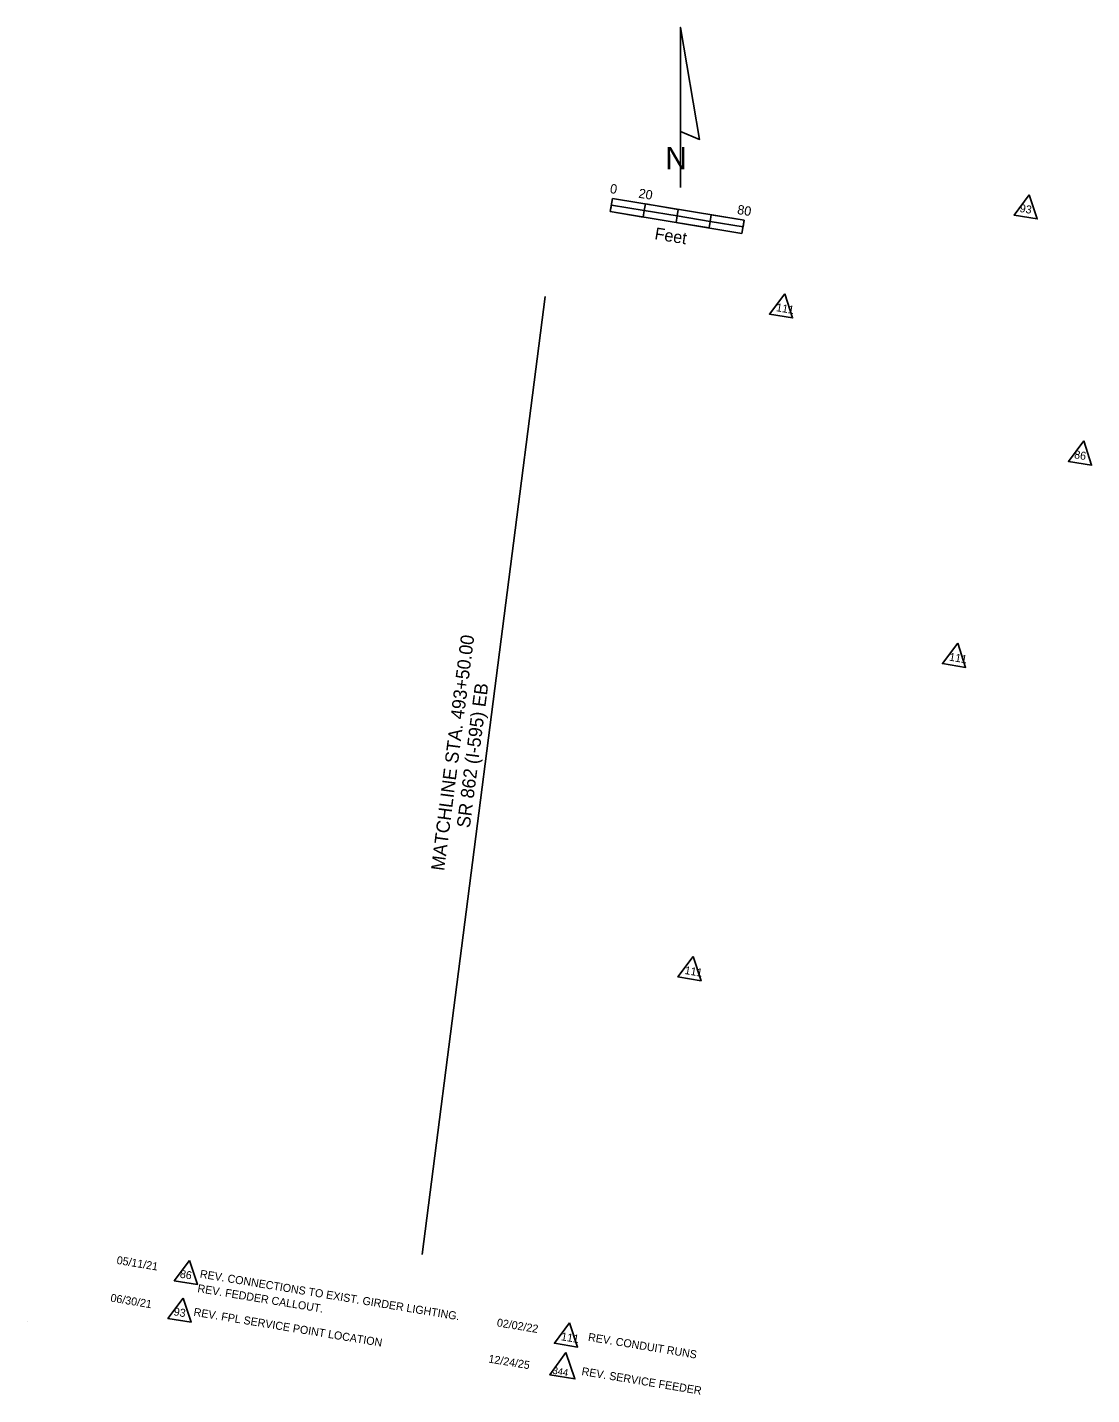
# Model space of a CAD drawing. Extents: x 927483 to 928746, y 636242 to 637203.
# Drawn here: x 927483 to 928122, y 636383 to 637203 of the extents above; entities that cross this region are included whole.
import ezdxf

# ---------------------------------------------------------------- set-up
doc = ezdxf.new("R2010")
doc.units = 0
for name, color, linetype in [('Cloud_dp', 7, 'Continuous'), ('NorthArw_dp', 7, 'Continuous'), ('PlotBorder_dp', 7, 'Continuous'), ('Scale_dp', 7, 'Continuous'), ('TextMinor', 7, 'Continuous')]:
    doc.layers.add(name, color=color, linetype=linetype)

msp = doc.modelspace()

# ---------------------------------------------------------------- linework, layer by layer
at = {"layer": 'Cloud_dp'}
for points in [[(928084.3, 637102.26), (928075.15, 637090.02), (928089.05, 637087.73)], [(927937.65, 637042.9), (927928.5, 637030.67), (927942.39, 637028.37)], [(928116.97, 636954.6), (928107.81, 636942.36), (928121.71, 636940.07)], [(928041.37, 636833.37), (928032.22, 636821.14), (928046.12, 636818.85)], [(927882.74, 636645.45), (927873.59, 636633.22), (927887.49, 636630.92)], [(927580.68, 636463.27), (927571.53, 636451.03), (927585.42, 636448.74)], [(927576.96, 636440.67), (927567.8, 636428.43), (927581.7, 636426.14)], [(927808.67, 636425.85), (927799.52, 636413.61), (927813.41, 636411.32)], [(927806.37, 636408.06), (927796.74, 636394.71), (927811.86, 636392.21)]]:
    msp.add_lwpolyline(points, close=True, dxfattribs=at)
at = {"layer": 'NorthArw_dp'}
msp.add_line((927875.11, 637106.63), (927875.11, 637202.63), dxfattribs=at)
msp.add_lwpolyline([(927875.11, 637140.23), (927875.11, 637202.63), (927886.63, 637135.43)], close=True, dxfattribs=at)
at = {"layer": 'PlotBorder_dp'}
msp.add_line((927794.09, 637041.24), (927720.24, 636466.75), dxfattribs=at)
at = {"layer": 'Scale_dp'}
for p, q in [((927834.37, 637100.01), (927833.07, 637092.11)), ((927913.31, 637086.99), (927834.37, 637100.01)), ((927833.07, 637092.11), (927912, 637079.1)), ((927912, 637079.1), (927913.31, 637086.99))]:
    msp.add_line(p, q, dxfattribs=at)
for points in [[(927853.45, 637092.81), (927854.11, 637096.75), (927873.84, 637093.5), (927873.19, 637089.55)], [(927833.07, 637092.11), (927833.72, 637096.06), (927853.45, 637092.81), (927852.8, 637088.86)], [(927872.54, 637085.61), (927873.19, 637089.55), (927892.92, 637086.3), (927892.27, 637082.35)], [(927892.92, 637086.3), (927893.57, 637090.25), (927913.31, 637086.99), (927912.66, 637083.05)]]:
    msp.add_lwpolyline(points, close=True, dxfattribs=at)
at = {"layer": 'TextMinor'}
msp.add_line((927483.47, 636426.68), (927483.47, 636426.68), dxfattribs=at)

# ---------------------------------------------------------------- texts
at = {"layer": 'Cloud_dp'}
for s, height, p in [('93', 4.8, (928078.28, 637091.95)), ('111', 4.8, (927932.25, 637032.49)), ('86', 4.8, (928110.95, 636944.29)), ('111', 4.8, (928035.98, 636822.96)), ('111', 4.8, (927877.35, 636635.04)), ('05/11/21', 4.8, (927536.77, 636461.2)), ('86', 4.8, (927574.66, 636452.96)), ('REV. CONNECTIONS TO EXIST. GIRDER LIGHTING. ', 4.8, (927586.68, 636452.97)), ('REV. FEDDER CALLOUT.', 4.8, (927585.24, 636444.29)), ('06/30/21', 4.8, (927533.05, 636438.6)), ('93', 4.8, (927570.93, 636430.36)), ('REV. FPL SERVICE POINT LOCATION', 4.8, (927582.91, 636430.14)), ('02/02/22', 4.8, (927764.76, 636423.78)), ('111', 4.8, (927803.27, 636415.44)), ('REV. CONDUIT RUNS', 4.8, (927819.47, 636415.08)), ('12/24/25', 4.8, (927759.73, 636402.07)), ('344', 4.2, (927798.19, 636395.32)), ('REV. SERVICE FEEDER', 4.8, (927815.58, 636394.55))]:
    msp.add_text(s, height=height, rotation=350.63813, dxfattribs=at).set_placement(p)
at = {"layer": 'NorthArw_dp'}
msp.add_text('N', height=13.43, dxfattribs=at).set_placement((927865.99, 637117.5))
at = {"layer": 'PlotBorder_dp'}
for s, p in [('MATCHLINE STA. 493+50.00', (927733.41, 636696.57)), ('SR 862 (I-595) EB', (927748.81, 636722.24))]:
    msp.add_text(s, height=8, rotation=82.67462, dxfattribs=at).set_placement(p)
at = {"layer": 'Scale_dp'}
for s, height, p in [('0', 5.6, (927832.56, 637103.35)), ('20', 5.6, (927849.7, 637100.52)), ('80', 5.6, (927908.88, 637090.76)), ('Feet', 7.2, (927859.28, 637075.63))]:
    msp.add_text(s, height=height, rotation=350.63813, dxfattribs=at).set_placement(p)

doc.saveas('drawing.dxf')
